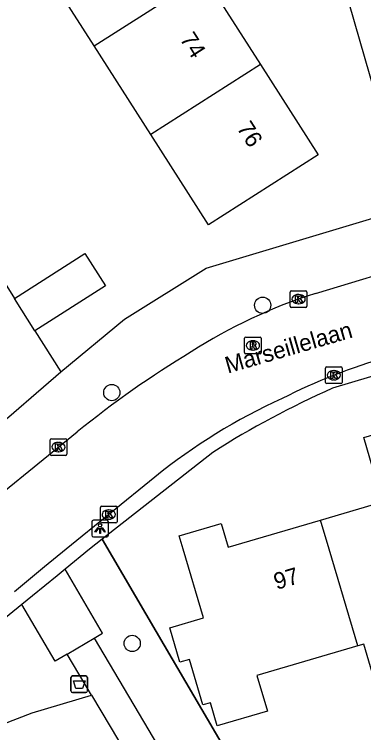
# Model space of a CAD drawing. Extents: x 158461 to 159795, y 387220 to 388672.
# Drawn here: x 158961.62 to 158982.61, y 387988.98 to 388032.14 of the extents above; entities that cross this region are included whole.
import ezdxf

# ---------------------------------------------------------------- set-up
doc = ezdxf.new("R2010")
doc.units = 0
for name, color, linetype in [('IMGEO_Afvalbak', 7, 'Continuous'), ('IMGEO_Boom', 7, 'Continuous'), ('IMGEO_Groenvoorziening', 7, 'Continuous'), ('IMGEO_Hek', 7, 'Continuous'), ('IMGEO_Kolk', 7, 'Continuous'), ('IMGEO_Lichtpunt', 7, 'Continuous'), ('IMGEO_Openbare_ruimte_label', 7, 'Continuous'), ('IMGEO_Pand', 7, 'Continuous'), ('IMGEO_Pand_nummerreeks', 7, 'Continuous'), ('IMGEO_Rijbaan_lokaal_open', 7, 'Continuous'), ('IMGEO_Rioolput', 7, 'Continuous'), ('IMGEO_Voetpad_halfverhard', 7, 'Continuous'), ('IMGEO_Voetpad_open', 7, 'Continuous')]:
    doc.layers.add(name, color=color, linetype=linetype)

msp = doc.modelspace()

# ---------------------------------------------------------------- linework, layer by layer
at = {"layer": 'IMGEO_Afvalbak'}
for p, q in [((158965.025, 387991.49), (158965.025, 387992.29)), ((158965.025, 387992.29), (158965.025, 387991.49)), ((158965.125, 387992.39), (158965.915, 387992.39)), ((158965.915, 387992.39), (158965.125, 387992.39)), ((158966.015, 387992.29), (158966.015, 387991.49)), ((158966.015, 387991.49), (158966.015, 387992.29)), ((158965.915, 387991.39), (158965.125, 387991.39)), ((158965.125, 387991.39), (158965.915, 387991.39))]:
    msp.add_line(p, q, dxfattribs=at)
msp.add_lwpolyline([(158965.168, 387992.104), (158965.872, 387992.104), (158965.723, 387991.634), (158965.317, 387991.634), (158965.168, 387992.104)], dxfattribs=at)
for centre, start, end in [((158965.125, 387992.29), 90, 180), ((158965.125, 387992.29), 90, 180), ((158965.915, 387992.29), 0, 90), ((158965.915, 387992.29), 360, 90), ((158965.125, 387991.49), 180, 270), ((158965.125, 387991.49), 180, 270), ((158965.915, 387991.49), 270, 0), ((158965.915, 387991.49), 270, 0)]:
    msp.add_arc(centre, 0.1, start, end, dxfattribs=at)
at = {"layer": 'IMGEO_Boom'}
for centre in [(158976.54, 388014.659), (158967.479, 388009.415), (158968.703, 387994.343)]:
    msp.add_circle(centre, 0.489, dxfattribs=at)
at = {"layer": 'IMGEO_Groenvoorziening'}
for points in [[(158966.901, 388000.614), (158970.146, 387995.067), (158980.01, 387978.204), (158992.494, 387982.207), (158992.422, 387982.522)], [(158954.948, 387981.466), (158957.93, 387986.48), (158959.268, 387988.263), (158960.939, 387989.488), (158962.688, 387990.168), (158966.256, 387991.241)]]:
    msp.add_lwpolyline(points, dxfattribs=at)
at = {"layer": 'IMGEO_Hek'}
for points in [[(158970.146, 387995.067), (158966.901, 388000.614)], [(158992.422, 387982.522), (158992.494, 387982.207), (158980.01, 387978.204), (158970.146, 387995.067)]]:
    msp.add_lwpolyline(points, dxfattribs=at)
at = {"layer": 'IMGEO_Kolk'}
for p, q in [((158978.199, 388014.6), (158978.199, 388015.452)), ((158978.274, 388015.526), (158979.126, 388015.526)), ((158979.2, 388015.452), (158979.2, 388014.6)), ((158978.687, 388015.306), (158978.712, 388015.306)), ((158979.126, 388014.526), (158978.274, 388014.526)), ((158978.71, 388014.746), (158978.685, 388014.746)), ((158980.317, 388010.028), (158980.317, 388010.88)), ((158980.392, 388010.954), (158981.244, 388010.954)), ((158980.805, 388010.734), (158980.83, 388010.734)), ((158981.318, 388010.88), (158981.318, 388010.028)), ((158981.244, 388009.954), (158980.392, 388009.954)), ((158980.828, 388010.174), (158980.803, 388010.174)), ((158963.776, 388005.717), (158963.776, 388006.569)), ((158963.851, 388006.643), (158964.703, 388006.643)), ((158964.264, 388006.423), (158964.289, 388006.423)), ((158964.777, 388006.569), (158964.777, 388005.717)), ((158964.703, 388005.643), (158963.851, 388005.643)), ((158964.287, 388005.863), (158964.262, 388005.863)), ((158966.796, 388001.656), (158966.796, 388002.508)), ((158966.871, 388002.582), (158967.723, 388002.582)), ((158967.797, 388002.508), (158967.797, 388001.656)), ((158967.284, 388002.362), (158967.309, 388002.362)), ((158967.723, 388001.582), (158966.871, 388001.582)), ((158967.307, 388001.802), (158967.282, 388001.802))]:
    msp.add_line(p, q, dxfattribs=at)
for points in [[(158978.199, 388014.6), (158978.199, 388015.452)], [(158978.274, 388015.526), (158979.126, 388015.526)], [(158979.2, 388015.452), (158979.2, 388014.6)], [(158978.52, 388015.226), (158978.643, 388015.226), (158978.643, 388015.075), (158978.773, 388015.226), (158978.937, 388015.226), (158978.791, 388015.075), (158978.944, 388014.826), (158978.792, 388014.826), (158978.707, 388014.99), (158978.643, 388014.923), (158978.643, 388014.826), (158978.52, 388014.826), (158978.52, 388015.226)], [(158979.126, 388014.526), (158978.274, 388014.526)], [(158980.317, 388010.028), (158980.317, 388010.88)], [(158980.392, 388010.954), (158981.244, 388010.954)], [(158980.638, 388010.654), (158980.761, 388010.654), (158980.761, 388010.503), (158980.891, 388010.654), (158981.055, 388010.654), (158980.909, 388010.503), (158981.062, 388010.254), (158980.91, 388010.254), (158980.825, 388010.418), (158980.761, 388010.351), (158980.761, 388010.254), (158980.638, 388010.254), (158980.638, 388010.654)], [(158981.318, 388010.88), (158981.318, 388010.028)], [(158981.244, 388009.954), (158980.392, 388009.954)], [(158963.776, 388005.717), (158963.776, 388006.569)], [(158963.851, 388006.643), (158964.703, 388006.643)], [(158964.097, 388006.343), (158964.22, 388006.343), (158964.22, 388006.192), (158964.35, 388006.343), (158964.514, 388006.343), (158964.368, 388006.192), (158964.521, 388005.943), (158964.369, 388005.943), (158964.284, 388006.107), (158964.22, 388006.04), (158964.22, 388005.943), (158964.097, 388005.943), (158964.097, 388006.343)], [(158964.777, 388006.569), (158964.777, 388005.717)], [(158964.703, 388005.643), (158963.851, 388005.643)], [(158966.796, 388001.656), (158966.796, 388002.508)], [(158966.871, 388002.582), (158967.723, 388002.582)], [(158967.797, 388002.508), (158967.797, 388001.656)], [(158967.117, 388002.282), (158967.24, 388002.282), (158967.24, 388002.131), (158967.37, 388002.282), (158967.534, 388002.282), (158967.388, 388002.131), (158967.541, 388001.882), (158967.389, 388001.882), (158967.304, 388002.046), (158967.24, 388001.979), (158967.24, 388001.882), (158967.117, 388001.882), (158967.117, 388002.282)], [(158967.723, 388001.582), (158966.871, 388001.582)]]:
    msp.add_lwpolyline(points, dxfattribs=at)
for centre, start, end in [((158978.276, 388015.45), 91.552, 178.448), ((158978.276, 388015.45), 91.552, 178.448), ((158979.124, 388015.45), 1.552, 88.448), ((158979.124, 388015.45), 1.552, 88.448), ((158978.276, 388014.602), 181.552, 268.448), ((158978.276, 388014.602), 181.552, 268.448), ((158979.124, 388014.602), 271.552, 358.448), ((158979.124, 388014.602), 271.552, 358.448), ((158980.394, 388010.878), 91.552, 178.448), ((158980.394, 388010.878), 91.552, 178.448), ((158981.242, 388010.878), 1.552, 88.448), ((158981.242, 388010.878), 1.552, 88.448), ((158980.394, 388010.03), 181.552, 268.448), ((158980.394, 388010.03), 181.552, 268.448), ((158981.242, 388010.03), 271.552, 358.448), ((158981.242, 388010.03), 271.552, 358.448), ((158963.853, 388006.567), 91.552, 178.448), ((158963.853, 388006.567), 91.552, 178.448), ((158964.701, 388006.567), 1.552, 88.448), ((158964.701, 388006.567), 1.552, 88.448), ((158963.853, 388005.719), 181.552, 268.448), ((158963.853, 388005.719), 181.552, 268.448), ((158964.701, 388005.719), 271.552, 358.448), ((158964.701, 388005.719), 271.552, 358.448), ((158966.873, 388002.506), 91.552, 178.448), ((158966.873, 388002.506), 91.552, 178.448), ((158967.721, 388002.506), 1.552, 88.448), ((158967.721, 388002.506), 1.552, 88.448), ((158966.873, 388001.658), 181.552, 268.448), ((158966.873, 388001.658), 181.552, 268.448), ((158967.721, 388001.658), 271.552, 358.448), ((158967.721, 388001.658), 271.552, 358.448)]:
    msp.add_arc(centre, 0.0765, start, end, dxfattribs=at)
for centre, major_axis, ratio, start_param, end_param in [((158978.686, 388015.026), (-0.387, 0.002), 0.722429, 4.712389, 7.853982), ((158978.711, 388015.026), (-0.39, 0.002), 0.717154, 1.570796, 4.712389), ((158980.804, 388010.454), (-0.387, 0.002), 0.722429, 4.712389, 7.853982), ((158980.829, 388010.454), (-0.39, 0.002), 0.717154, 1.570796, 4.712389), ((158964.263, 388006.143), (-0.387, 0.002), 0.722429, 4.712389, 7.853982), ((158964.288, 388006.143), (-0.39, 0.002), 0.717154, 1.570796, 4.712389), ((158967.283, 388002.082), (-0.387, 0.002), 0.722429, 4.712389, 7.853982), ((158967.308, 388002.082), (-0.39, 0.002), 0.717154, 1.570796, 4.712389)]:
    msp.add_ellipse(centre, major_axis=major_axis, ratio=ratio, start_param=start_param, end_param=end_param, dxfattribs=at)
at = {"layer": 'IMGEO_Lichtpunt'}
for p, q in [((158966.278, 388001.648), (158966.278, 388000.841)), ((158966.278, 388001.648), (158966.278, 388000.841)), ((158967.18, 388001.743), (158966.372, 388001.743)), ((158967.18, 388001.743), (158966.372, 388001.743)), ((158967.274, 388000.841), (158967.274, 388001.648)), ((158967.274, 388000.841), (158967.274, 388001.648)), ((158966.372, 388000.747), (158967.18, 388000.747)), ((158966.372, 388000.747), (158967.18, 388000.747))]:
    msp.add_line(p, q, dxfattribs=at)
for points in [[(158966.652, 388001.312), (158966.691, 388001.284), (158966.503, 388001.022), (158966.465, 388001.049), (158966.652, 388001.312)], [(158966.754, 388001.264), (158966.801, 388001.264), (158966.801, 388000.942), (158966.754, 388000.942), (158966.754, 388001.264)], [(158966.864, 388001.284), (158966.902, 388001.311), (158967.089, 388001.049), (158967.05, 388001.021), (158966.864, 388001.284)]]:
    msp.add_lwpolyline(points, dxfattribs=at)
msp.add_circle((158966.777, 388001.446), 0.0994, dxfattribs=at)
for centre, start, end in [((158966.372, 388001.648), 90, 180), ((158966.372, 388001.648), 90, 180), ((158967.18, 388001.648), 0, 90), ((158967.18, 388001.648), 0, 90), ((158966.372, 388000.841), 180, 270), ((158966.372, 388000.841), 180, 270), ((158967.18, 388000.841), 270, 0), ((158967.18, 388000.841), 270, 360)]:
    msp.add_arc(centre, 0.0946, start, end, dxfattribs=at)
at = {"layer": 'IMGEO_Pand'}
for points in [[(158966.421, 388030.248), (158963.019, 388035.573)], [(158966.421, 388030.248), (158973.004, 388034.453)], [(158973.004, 388034.453), (158976.407, 388029.127)], [(158969.824, 388024.922), (158966.421, 388030.248)], [(158976.407, 388029.127), (158979.874, 388023.701), (158973.291, 388019.495), (158969.824, 388024.922)], [(158976.407, 388029.127), (158969.824, 388024.922)], [(158961.626, 388015.063), (158965.858, 388017.766), (158967.092, 388015.835), (158962.86, 388013.132)], [(158962.86, 388013.132), (158961.626, 388015.063)], [(158980.02, 388001.757), (158983.749, 388002.858), (158982.612, 388006.709), (158984.927, 388007.393)], [(158982.251, 387994.201), (158976.196, 387992.413), (158976.825, 387990.282), (158973.81, 387989.391), (158973.4, 387990.779), (158972.948, 387990.646), (158972.139, 387993.383), (158971.571, 387993.215), (158970.959, 387995.287), (158972.984, 387995.885), (158971.769, 388000), (158971.533, 388000.799), (158974.045, 388001.541), (158974.465, 388000.117), (158980.02, 388001.757)], [(158982.251, 387994.201), (158980.539, 388000), (158980.02, 388001.757)], [(158989.253, 387992.738), (158989.444, 387992.091), (158983.762, 387990.414), (158982.613, 387994.308), (158982.251, 387994.201)]]:
    msp.add_lwpolyline(points, dxfattribs=at)
at = {"layer": 'IMGEO_Rijbaan_lokaal_open'}
for points in [[(158983.636, 388026.21), (158979.834, 388039.422), (158976.999, 388043.709), (158973.223, 388043.221), (158953.249, 388074.447)], [(158957.321, 388021.953), (158961.626, 388015.063)], [(158979.711, 388015.369), (158992.404, 388019.209), (158993.461, 388019.524)], [(158962.86, 388013.132), (158964.414, 388010.658)], [(158960.09, 388006.937), (158964.414, 388010.658)], [(158958.396, 388001.361), (158965.397, 388007.054)], [(158970.063, 388004.333), (158964.743, 388000), (158963.444, 387998.942), (158961.624, 387997.441)]]:
    msp.add_lwpolyline(points, dxfattribs=at)
for centre, radius, start, end in [((158989.33, 387985.235), 31.632, 107.7044, 122.6927), ((159004.265, 387958.909), 61.876, 121.16383, 128.91449), ((158993.273, 387978.607), 34.195, 105.6194, 117.0729), ((158992.315, 387976.849), 35.363, 114.3946, 128.9958)]:
    msp.add_arc(centre, radius, start, end, dxfattribs=at)
at = {"layer": 'IMGEO_Rioolput'}
for p, q in [((158975.456, 388011.822), (158975.456, 388012.674)), ((158975.531, 388012.748), (158976.383, 388012.748)), ((158975.944, 388012.528), (158975.969, 388012.528)), ((158976.457, 388012.674), (158976.457, 388011.822)), ((158975.967, 388011.968), (158975.942, 388011.968)), ((158976.383, 388011.748), (158975.531, 388011.748))]:
    msp.add_line(p, q, dxfattribs=at)
for points in [[(158975.456, 388011.822), (158975.456, 388012.674)], [(158975.531, 388012.748), (158976.383, 388012.748)], [(158976.045, 388012.446), (158975.793, 388012.448), (158975.793, 388012.048)], [(158975.971, 388012.367), (158975.917, 388012.367), (158975.917, 388012.286)], [(158976.457, 388012.674), (158976.457, 388011.822)], [(158975.793, 388012.048), (158975.917, 388012.048), (158975.917, 388012.21), (158975.928, 388012.21)], [(158975.917, 388012.286), (158975.969, 388012.286)], [(158975.975, 388012.181), (158976.046, 388012.048), (158976.186, 388012.048), (158976.121, 388012.174)], [(158976.383, 388011.748), (158975.531, 388011.748)]]:
    msp.add_lwpolyline(points, dxfattribs=at)
for centre, radius, start, end in [((158975.533, 388012.672), 0.0765, 91.552, 178.448), ((158975.533, 388012.672), 0.0765, 91.552, 178.448), ((158975.977, 388012.271), 0.0964, 77.0061, 93.1865), ((158975.991, 388012.328), 0.0378, 276.6634, 79.6772), ((158976.044, 388012.336), 0.109, 350.3612, 89.416), ((158976.381, 388012.672), 0.0765, 1.552, 88.448), ((158976.381, 388012.672), 0.0765, 1.552, 88.448), ((158975.927, 388012.157), 0.0533, 26.0293, 88.6989), ((158975.953, 388012.475), 0.19, 274.7715, 282.9687), ((158976.042, 388012.336), 0.112, 277.5842, 350.9817), ((158976.026, 388012.121), 0.108, 29.5134, 73.7905), ((158975.533, 388011.824), 0.0765, 181.552, 268.448), ((158975.533, 388011.824), 0.0765, 181.552, 268.448), ((158976.381, 388011.824), 0.0765, 271.552, 358.448), ((158976.381, 388011.824), 0.0765, 271.552, 358.448)]:
    msp.add_arc(centre, radius, start, end, dxfattribs=at)
for centre, major_axis, ratio, start_param, end_param in [((158975.943, 388012.248), (-0.387, 0.002), 0.722429, 4.712389, 7.853982), ((158975.968, 388012.248), (-0.39, 0.002), 0.717154, 1.570796, 4.712389)]:
    msp.add_ellipse(centre, major_axis=major_axis, ratio=ratio, start_param=start_param, end_param=end_param, dxfattribs=at)
at = {"layer": 'IMGEO_Voetpad_halfverhard'}
for points in [[(158966.416, 387994.664), (158978.862, 387973.647)], [(158966.256, 387991.241), (158964.791, 387993.7)], [(158966.256, 387991.241), (158974.983, 387976.585)]]:
    msp.add_lwpolyline(points, dxfattribs=at)
at = {"layer": 'IMGEO_Voetpad_open'}
for points in [[(158964.414, 388010.658), (158968.239, 388013.827), (158973.147, 388016.881), (158983.552, 388020.004)], [(159004.064, 388016.625), (159000, 388015.421), (158980.738, 388009.673)], [(158973.551, 388005.82), (158966.901, 388000.614)], [(158966.901, 388000.614), (158966.147, 388000), (158964.673, 387998.799)], [(158964.673, 387998.799), (158964.197, 387998.411), (158962.708, 387997.199), (158962.066, 387996.676)], [(158966.416, 387994.664), (158966.923, 387994.965), (158964.673, 387998.799)], [(158962.066, 387996.676), (158953.387, 387989.609)], [(158964.791, 387993.7), (158964.078, 387993.277), (158962.066, 387996.676)], [(158964.791, 387993.7), (158966.416, 387994.664)]]:
    msp.add_lwpolyline(points, dxfattribs=at)
msp.add_arc((159002.442, 387960.56), 53.695, 113.8411, 122.551, dxfattribs=at)

# ---------------------------------------------------------------- texts
at = {"layer": 'IMGEO_Openbare_ruimte_label'}
msp.add_text('Marseillelaan', height=1, rotation=16.1342, dxfattribs=at).set_placement((158974.448, 388010.552))
at = {"layer": 'IMGEO_Pand_nummerreeks'}
for s, rotation, p in [('74', 302.5807, (158971.536, 388030.657)), ('76', 302.5807, (158974.956, 388025.307)), ('97', 16.4496, (158977.378, 387997.557))]:
    msp.add_text(s, height=1, rotation=rotation, dxfattribs=at).set_placement(p)

doc.saveas('drawing.dxf')
